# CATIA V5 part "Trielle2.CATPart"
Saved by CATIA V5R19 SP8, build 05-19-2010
Part number: Trielle
Bounding box of the stored display mesh (mm): x -300 to 20, y 0 to 50, z -30 to 30
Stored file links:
  F:\Travail\2e année\IAO\Projet\Trielle2.CATPart
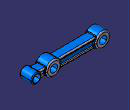
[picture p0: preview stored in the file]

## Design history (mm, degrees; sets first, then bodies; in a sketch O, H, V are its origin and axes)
Set1
  Plane1: type Offset, RefPlane yz-plane, Offset 70, reversed
Body1 (main body)
  Sketch1 on zx-plane, origin (0, 0, 0), H (-1, 0, 0), V (0, 0, 1)
    circle A1 centre (0, 0) radius 20
    circle A2 centre (70, 0) radius 30
    point P1 (70, 0)
    circle A3 centre (270, 0) radius 30
    point P2 (270, 0)
    radius A3 = 30
    radius A2 = 30
    radius A1 = 20
    distance O P1 = 70
    distance P2 P1 = 200
    coincidence: P1 H, P2 H
  Pad1: profile Sketch1, direction (0, 1, 0), length 50
  Sketch2 on yz-plane, origin (0, 0, 0), H (0, 1, 0), V (0, 0, 1)
    line L1 (10, 7) -> (5, 7)
    line L2 (40, 7) -> (40, -7)
    line L3 (40, -7) -> (45, -7)
    line L4 (10, -7) -> (10, 7)
    point P5 (5, 7)
    line L5 (45, 7) -> (45, 15)
    line L6 (45, 15) -> (5, 15)
    line L7 (5, 15) -> (5, 7)
    point P6 (45, 7)
    point P7 (45, 15)
    point P8 (5, 15)
    axis line L8 (-6.6001, 0) -> (69.3419, 0)
    point P11 (45, -15)
    point P12 (45, -7)
    line L9 (45, -7) -> (45, -15)
    point P13 (5, -15)
    point P14 (5, -7)
    line L10 (5, -15) -> (5, -7)
    line L11 (45, 7) -> (40, 7)
    line L12 (5, -7) -> (10, -7)
    point P15 (5, -15)
    point P16 (45, -15)
    line L13 (45, -15) -> (5, -15)
    reference projected line E1 (50, 20) -> (50, -20) from edge [face of Pad1 from Sketch1.A1 | end face of Pad1]
    reference projected line E2 (0, 20) -> (0, -20) from edge [start face of Pad1 | face of Pad1 from Sketch1.A1]
    distance L5 E1 = 5
    distance L7 E2 = 5
    distance L8 L11 = 7
    distance L2 L4 = 30
    distance L2 L5 = 5
    distance L6 L8 = 15
    horizontal: L1 H, L3 H, L6 H, L8 H, L11 H, L12 H
    vertical: L2 V, L4 V, L5 V, L7 V
    symmetry: P7 P11 L8, P6 P12 L8, L5 L9 L8, P8 P13 L8, P5 P14 L8, L7 L10 L8, P8 P15 L8, P7 P16 L8, L6 L13 L8
    coincidence: L1 L11, L3 L12, H L8
  Pad2: profile Sketch2, direction (-1, 0, 0), length 70
  Sketch3 on end face of Pad1, origin (6.1028, 50, 9.6712), H (1, 0, 0), V (0, 0, -1)
    point P1 (-6.1028, 9.6712)
    reference projected circle E1 centre (-6.1028, 9.6712) radius 20 from edge [face of Pad1 from Sketch1.A1 | end face of Pad1]
    concentricity: P1 E1
  Hole1: placed by Sketch3, at (0, 50, 0) direction (0, -1, 0), diameter 30, through (limit type 6)
  Fillet1: radius 10, on edge [face of Pad1 from Sketch1.A2 | face of Pad2] (x2); edge [face of Pad2 | face of Pad1 from Sketch1.A2] (x2); edge [face of Pad2 | face of Pad1 from Sketch1.A3]; edge [face of Pad1 from Sketch1.A3 | face of Pad2], deactivated
  Fillet2: radius 3, on edge [start face of Pad1 | face of Pad1 from Sketch1.A1]; edge [face of Pad1 from Sketch1.A1 | end face of Pad1]
  Sketch4 on Plane1, origin (-70, 0, 0), H (0, 1, 0), V (0, 0, 1)
    line L1 (5, 20) -> (45, 20)
    line L2 (45, 20) -> (45, 10)
    line L3 (45, -20) -> (5, -20)
    line L4 (5, -20) -> (5, -10)
    point P5 (5, 10)
    line L5 (5, 10) -> (10, 10)
    line L6 (10, 10) -> (10, -10)
    line L7 (10, -10) -> (5, -10)
    point P9 (45, 10)
    line L8 (45, 10) -> (40, 10)
    line L9 (40, 10) -> (40, -10)
    line L10 (40, -10) -> (45, -10)
    point P11 (40, -10)
    line L11 (45, -10) -> (45, -20)
    line L12 (5, 10) -> (5, 20)
    reference intersected line E1 (50, 30) -> (50, -30) from end face of Pad1
    reference intersected line E2 (0, -30) -> (0, 30) from start face of Pad1
    length L9 = 20
    length L2 = 10
    length L11 = 10
    distance L9 L11 = 5
    length L7 = 5
    distance H L7 = 10
    distance L2 E1 = 5
    distance L4 E2 = 5
    horizontal: L1 H, L3 H, L5 H, L7 H, L8 H, L10 H
    vertical: L2 V, L4 V, L6 V, L9 V, L11 V, L12 V
    coincidence: P5 L4, P9 L5, P11 L7, L2 L11, L4 L12
  Pad3: profile Sketch4, direction (-1, 0, 0), length 200
  Sketch5 on end face of Pad1, origin (-82.2766, 50, 0), H (1, 0, 0), V (0, 0, -1)
    point P1 (12.2766, 0)
    reference projected circle E1 centre (12.2766, 0) radius 30 from edge [face of Pad1 from Sketch1.A2 | end face of Pad1]
    concentricity: P1 E1
  Hole2: placed by Sketch5, at (-70, 50, 0) direction (0, -1, 0), diameter 30, through (limit type 6)
  Sketch6 on end face of Pad1, origin (-273.6474, 50, 9.5601), H (1, 0, 0), V (0, 0, -1)
    point P1 (3.6474, 9.5601)
    reference projected circle E1 centre (3.6474, 9.5601) radius 30 from edge [face of Pad1 from Sketch1.A3 | end face of Pad1]
    concentricity: P1 E1
  Hole3: placed by Sketch6, at (-270, 50, 0) direction (0, -1, 0), diameter 30, through (limit type 6)
  Fillet3: radius 5, on edge [face of Pad1 from Sketch1.A2 | end face of Pad1]; edge [start face of Pad1 | face of Pad1 from Sketch1.A2]; edge [start face of Pad1 | face of Pad1 from Sketch1.A3]; edge [face of Pad1 from Sketch1.A3 | end face of Pad1]
  Fillet4: radius 5, on edge [face of Pad3 from Sketch4.L1 | face of Pad3 from Sketch4.L12]; edge [face of Pad3 from Sketch4.L2 | face of Pad3 from Sketch4.L1]; edge [face of Pad3 from Sketch4.L3 | face of Pad3 from Sketch4.L11]; edge [face of Pad3 from Sketch4.L4 | face of Pad3 from Sketch4.L3]; edge [face of Pad2 from Sketch2.L10 | face of Pad2 from Sketch2.L13]; edge [face of Pad2 from Sketch2.L13 | face of Pad2 from Sketch2.L9]; edge [face of Pad2 from Sketch2.L5 | face of Pad2 from Sketch2.L6]; edge [face of Pad2 from Sketch2.L6 | face of Pad2 from Sketch2.L7]
  Fillet5: radius 3, on edge [face of Pad3 from Sketch4.L7 | face of Pad3 from Sketch4.L4]; edge [face of Pad3 from Sketch4.L12 | face of Pad3 from Sketch4.L5]; edge [face of Pad3 from Sketch4.L5 | face of Pad3 from Sketch4.L6]; edge [face of Pad3 from Sketch4.L6 | face of Pad3 from Sketch4.L7]; edge [face of Pad3 from Sketch4.L8 | face of Pad3 from Sketch4.L2]; edge [face of Pad3 from Sketch4.L9 | face of Pad3 from Sketch4.L8]; edge [face of Pad3 from Sketch4.L10 | face of Pad3 from Sketch4.L9]; edge [face of Pad3 from Sketch4.L11 | face of Pad3 from Sketch4.L10]
  Fillet6: radius 3, on edge [face of Pad2 from Sketch2.L11 | face of Pad2 from Sketch2.L5]; edge [face of Pad2 from Sketch2.L9 | face of Pad2 from Sketch2.L3]; edge [face of Pad2 from Sketch2.L12 | face of Pad2 from Sketch2.L10]; edge [face of Pad2 from Sketch2.L7 | face of Pad2 from Sketch2.L1]; edge [face of Pad2 from Sketch2.L1 | face of Pad2 from Sketch2.L4]; edge [face of Pad2 from Sketch2.L3 | face of Pad2 from Sketch2.L2]; edge [face of Pad2 from Sketch2.L2 | face of Pad2 from Sketch2.L11]; edge [face of Pad2 from Sketch2.L4 | face of Pad2 from Sketch2.L12]
  Fillet7: radius 3, on edge [face of Pad1 from Sketch1.A1 | face of Pad2 from Sketch2.L4]; edge [face of Pad1 | face of Pad2 from Sketch2.L4]
  Fillet8: radius 5, on edge [face of Pad1 from Sketch1.A2 | face of Pad3 from Sketch4.L6]; edge [face of Pad1 | face of Pad3 from Sketch4.L6]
